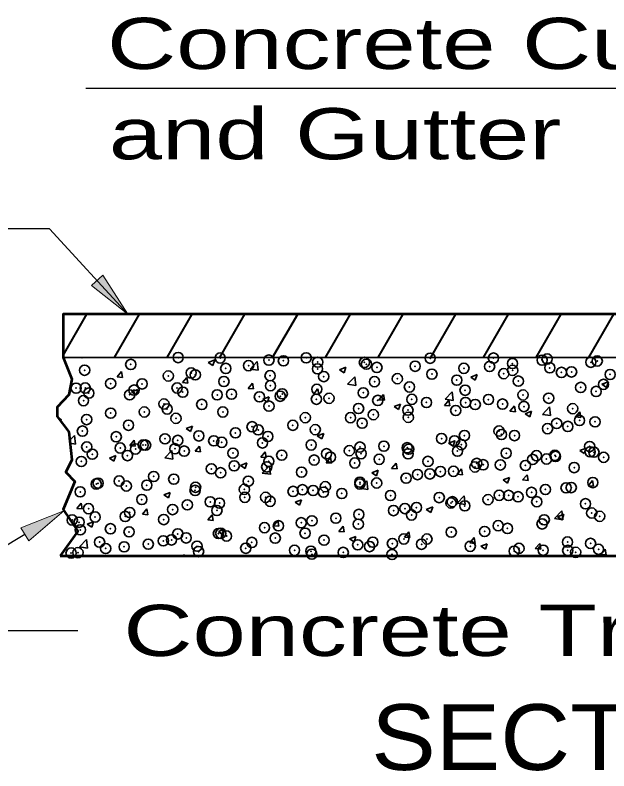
# Model space of a CAD drawing. Extents: x 14 to 49.3, y 28 to 50.
# Drawn here: x 25.937 to 27.563, y 46.498 to 48.567 of the extents above; entities that cross this region are included whole.
import ezdxf

# ---------------------------------------------------------------- set-up
doc = ezdxf.new("R2010")
doc.units = 0
doc.header["$LTSCALE"] = 0.056
doc.header["$PDMODE"] = 32
doc.header["$PDSIZE"] = 0.028
doc.layers.add('1', color=7, linetype='Continuous', lineweight=35)
doc.layers.add('3', color=7, linetype='Continuous', lineweight=13)

msp = doc.modelspace()

# ---------------------------------------------------------------- hatches: boundary and pattern name
at = {"layer": '3'}
for points in [[(26.17692, 47.85458), (26.14625, 47.8265), (26.246, 47.74833), (26.246, 47.74833)], [(25.95292, 47.16325), (25.97433, 47.1275), (26.07075, 47.20975), (26.07075, 47.20975)]]:
    msp.add_hatch(color=256, dxfattribs=at).paths.add_polyline_path(points)

# ---------------------------------------------------------------- linework, layer by layer
at = {"layer": '1', "lineweight": 40}
for p, q in [((26.06825, 47.63525), (26.1335, 47.74833)), ((26.20925, 47.62942), (26.27783, 47.74833)), ((26.35358, 47.62942), (26.42217, 47.74833)), ((26.49792, 47.62942), (26.5665, 47.74833)), ((26.64225, 47.62942), (26.71083, 47.74833)), ((26.78658, 47.62942), (26.85517, 47.74833)), ((26.93092, 47.62942), (26.9995, 47.74833)), ((27.07525, 47.62942), (27.14383, 47.74833)), ((27.21958, 47.62942), (27.28817, 47.74833)), ((27.36392, 47.62942), (27.4325, 47.74833)), ((27.50825, 47.62942), (27.57683, 47.74833))]:
    msp.add_line(p, q, dxfattribs=at)
at = {"layer": '1'}
for p, q in [((28.99683, 47.62942), (26.06825, 47.62942)), ((26.11692, 47.62942), (26.11925, 47.62783)), ((26.11925, 47.62783), (26.11975, 47.62942)), ((26.46608, 47.61625), (26.48358, 47.623)), ((26.46608, 47.61625), (26.4785, 47.60783)), ((26.4785, 47.60783), (26.48358, 47.62292)), ((26.58058, 47.59808), (26.60008, 47.61833)), ((26.60283, 47.59458), (26.60008, 47.61833)), ((26.58058, 47.59808), (26.60283, 47.59458)), ((26.82533, 47.59625), (26.84283, 47.60292)), ((26.82533, 47.59625), (26.83783, 47.58783)), ((26.83783, 47.58783), (26.84292, 47.60292)), ((26.21617, 47.57658), (26.22825, 47.59092)), ((26.21617, 47.57658), (26.23108, 47.57525)), ((26.23108, 47.57525), (26.22825, 47.59092)), ((26.3955, 47.56083), (26.4075, 47.57525)), ((26.41042, 47.55958), (26.40758, 47.57525)), ((26.84742, 47.55667), (26.86692, 47.577)), ((26.86967, 47.55325), (26.86692, 47.577)), ((27.18467, 47.57617), (27.20217, 47.58292)), ((27.18467, 47.57617), (27.19708, 47.56783)), ((27.19708, 47.56783), (27.20217, 47.58292)), ((26.3955, 47.56083), (26.41042, 47.55958)), ((26.57483, 47.54517), (26.58683, 47.55958)), ((26.58975, 47.54383), (26.58683, 47.5595)), ((26.84742, 47.55667), (26.86967, 47.55325)), ((27.54392, 47.55617), (27.56142, 47.56292)), ((27.54392, 47.55617), (27.55633, 47.54775)), ((27.55642, 47.54775), (27.56142, 47.56292)), ((26.256, 47.53558), (26.2735, 47.54233)), ((26.256, 47.53558), (26.2685, 47.52725)), ((26.2685, 47.52725), (26.27358, 47.54233)), ((26.57483, 47.54517), (26.58975, 47.54392)), ((26.75408, 47.5295), (26.76617, 47.54383)), ((26.76908, 47.52817), (26.76617, 47.54383)), ((27.11425, 47.51533), (27.13367, 47.53558)), ((27.1365, 47.51183), (27.13367, 47.53558)), ((26.61533, 47.51558), (26.63283, 47.52233)), ((26.61533, 47.51558), (26.62775, 47.50717)), ((26.62775, 47.50717), (26.63283, 47.52233)), ((26.75408, 47.5295), (26.76908, 47.52817)), ((26.93342, 47.51383), (26.9455, 47.52817)), ((26.93342, 47.51383), (26.94833, 47.5125)), ((26.94842, 47.5125), (26.9455, 47.52817)), ((27.11275, 47.49808), (27.12483, 47.5125)), ((27.11425, 47.51533), (27.13642, 47.51183)), ((27.12767, 47.49683), (27.12483, 47.5125)), ((26.97458, 47.49558), (26.99208, 47.50225)), ((26.97458, 47.49558), (26.987, 47.48717)), ((26.98708, 47.48717), (26.99208, 47.50225)), ((27.11275, 47.49808), (27.12767, 47.49683)), ((27.29208, 47.48242), (27.30408, 47.49683)), ((27.307, 47.48108), (27.30408, 47.49675)), ((27.381, 47.47392), (27.4005, 47.49425)), ((27.40325, 47.4705), (27.4005, 47.49425)), ((27.29208, 47.48242), (27.307, 47.48108)), ((27.33392, 47.4755), (27.35142, 47.48225)), ((27.33392, 47.4755), (27.34633, 47.46717)), ((27.34633, 47.46717), (27.35142, 47.48225)), ((27.381, 47.47392), (27.40325, 47.4705)), ((27.47133, 47.46675), (27.48342, 47.48108)), ((27.48633, 47.46542), (27.48342, 47.48108)), ((26.05842, 47.45975), (26.0635, 47.46167)), ((26.0615, 47.45575), (26.0635, 47.46167)), ((27.47133, 47.46675), (27.48633, 47.46542)), ((26.40525, 47.43492), (26.42275, 47.44167)), ((26.40525, 47.43492), (26.41767, 47.42658)), ((26.41767, 47.42658), (26.42275, 47.44167)), ((26.08683, 47.40292), (26.09958, 47.41625)), ((26.10233, 47.3925), (26.09958, 47.41617)), ((26.7645, 47.41492), (26.78208, 47.42167)), ((26.7645, 47.41492), (26.777, 47.40658)), ((26.777, 47.4065), (26.78208, 47.42167)), ((26.08767, 47.39475), (26.10233, 47.3925)), ((26.25083, 47.3885), (26.26292, 47.40283)), ((26.25083, 47.3885), (26.26583, 47.38717)), ((26.26583, 47.38717), (26.26292, 47.40283)), ((26.43017, 47.37283), (26.44225, 47.38717)), ((26.44517, 47.3715), (26.44225, 47.38717)), ((27.12383, 47.39492), (27.14133, 47.40167)), ((27.12383, 47.39492), (27.13625, 47.3865)), ((27.13625, 47.3865), (27.14133, 47.40158)), ((26.34692, 47.3545), (26.36642, 47.37483)), ((26.34692, 47.3545), (26.36642, 47.37483)), ((26.36917, 47.35108), (26.36642, 47.37483)), ((26.43017, 47.37283), (26.44508, 47.3715)), ((26.6095, 47.35717), (26.6215, 47.3715)), ((26.62442, 47.35583), (26.62158, 47.3715)), ((27.48308, 47.37492), (27.50058, 47.38158)), ((27.48308, 47.37492), (27.4955, 47.3665)), ((27.49558, 47.3665), (27.50058, 47.38158)), ((26.19517, 47.35433), (26.21267, 47.361)), ((26.19517, 47.35433), (26.20767, 47.34592)), ((26.20767, 47.34592), (26.21275, 47.361)), ((26.34692, 47.3545), (26.36917, 47.35108)), ((26.6095, 47.35717), (26.62442, 47.35583)), ((26.78883, 47.34142), (26.80083, 47.35583)), ((26.80375, 47.34017), (26.80083, 47.35583)), ((26.5545, 47.33433), (26.572, 47.341)), ((26.5545, 47.33433), (26.56692, 47.32592)), ((26.56692, 47.32592), (26.572, 47.341)), ((26.61375, 47.31317), (26.63325, 47.33342)), ((26.636, 47.30967), (26.63325, 47.33342)), ((26.78883, 47.34142), (26.80375, 47.34017)), ((26.96808, 47.32575), (26.98017, 47.34008)), ((26.96808, 47.32575), (26.98308, 47.32442)), ((26.98308, 47.32442), (26.98017, 47.34008)), ((27.14742, 47.31008), (27.1595, 47.32442)), ((27.16242, 47.30875), (27.1595, 47.32442)), ((26.61375, 47.31317), (26.636, 47.30975)), ((26.91375, 47.31425), (26.93125, 47.321)), ((26.91375, 47.31425), (26.92617, 47.30592)), ((26.92625, 47.30592), (26.93125, 47.321)), ((27.14742, 47.31008), (27.16233, 47.30875)), ((27.32675, 47.29442), (27.33883, 47.30875)), ((27.34167, 47.29308), (27.33883, 47.30875)), ((26.88058, 47.27175), (26.9, 47.29208)), ((26.90283, 47.26833), (26.9, 47.29208)), ((27.27308, 47.29425), (27.29058, 47.301)), ((27.27308, 47.29425), (27.2855, 47.28583)), ((27.2855, 47.28583), (27.29058, 47.301)), ((27.32675, 47.29442), (27.34167, 47.29308)), ((27.50608, 47.27867), (27.51808, 47.29308)), ((27.521, 47.27742), (27.51817, 47.29308)), ((26.88058, 47.27175), (26.90275, 47.26833)), ((27.50608, 47.27867), (27.521, 47.27742)), ((26.34442, 47.25367), (26.36192, 47.26042)), ((26.34442, 47.25367), (26.35683, 47.24525)), ((26.35692, 47.24525), (26.36192, 47.26042)), ((27.14733, 47.23042), (27.16683, 47.25067)), ((27.16958, 47.22692), (27.16683, 47.25067)), ((26.10625, 47.21617), (26.11825, 47.2305)), ((26.12117, 47.21483), (26.11833, 47.2305)), ((26.70367, 47.23367), (26.72125, 47.24033)), ((26.70367, 47.23367), (26.71617, 47.22525)), ((26.71617, 47.22525), (26.72125, 47.24033)), ((27.14733, 47.23042), (27.16958, 47.22692)), ((26.10625, 47.21617), (26.12117, 47.21483)), ((26.2855, 47.2005), (26.29758, 47.21483)), ((26.2855, 47.2005), (26.3005, 47.19917)), ((26.3005, 47.19917), (26.29758, 47.21483)), ((27.063, 47.21358), (27.0805, 47.22033)), ((27.063, 47.21358), (27.07542, 47.20525)), ((27.07542, 47.20525), (27.0805, 47.22033)), ((27.41417, 47.189), (27.43367, 47.20933)), ((27.42225, 47.19358), (27.43975, 47.20033)), ((27.43642, 47.18558), (27.43367, 47.20933)), ((27.43475, 47.18517), (27.43983, 47.20033)), ((26.13433, 47.173), (26.15183, 47.17975)), ((26.14683, 47.16467), (26.15192, 47.17975)), ((26.46483, 47.18475), (26.47692, 47.19917)), ((26.46483, 47.18475), (26.47983, 47.1835)), ((26.47983, 47.18342), (26.47692, 47.19917)), ((26.64417, 47.16908), (26.65625, 47.18342)), ((26.65917, 47.16775), (26.65625, 47.18342)), ((27.41417, 47.189), (27.43642, 47.18558)), ((27.42225, 47.19358), (27.43467, 47.18525)), ((26.13433, 47.173), (26.14683, 47.16467)), ((26.49367, 47.153), (26.51117, 47.15975)), ((26.50608, 47.14458), (26.51117, 47.15975)), ((26.64417, 47.16908), (26.65908, 47.16775)), ((26.8235, 47.15342), (26.8355, 47.16775)), ((26.83842, 47.15208), (26.83558, 47.16775)), ((26.49367, 47.153), (26.50608, 47.14458)), ((26.8235, 47.15342), (26.83842, 47.15208)), ((26.85292, 47.133), (26.87042, 47.13967)), ((26.86542, 47.12458), (26.87042, 47.13967)), ((27.00283, 47.13775), (27.01483, 47.15208)), ((27.00283, 47.13775), (27.01775, 47.13642)), ((27.01775, 47.13642), (27.01483, 47.15208)), ((26.11325, 47.111), (26.13275, 47.13133)), ((26.1355, 47.10758), (26.13275, 47.13133)), ((26.85292, 47.133), (26.86533, 47.12458)), ((27.18208, 47.122), (27.19417, 47.13642)), ((27.18208, 47.122), (27.19708, 47.12075)), ((27.19708, 47.12067), (27.19417, 47.13642)), ((27.21225, 47.113), (27.22975, 47.11967)), ((27.22467, 47.10458), (27.22975, 47.11967)), ((27.36142, 47.10633), (27.3735, 47.12067)), ((27.37642, 47.105), (27.3735, 47.12067)), ((26.11325, 47.111), (26.1355, 47.10758)), ((27.21225, 47.113), (27.22467, 47.10458)), ((27.36142, 47.10633), (27.37642, 47.105)), ((27.54075, 47.09067), (27.55283, 47.105)), ((27.55567, 47.08933), (27.55283, 47.105)), ((26.39592, 47.08617), (26.39958, 47.08992)), ((26.4, 47.08617), (26.39958, 47.08992)), ((27.54075, 47.09067), (27.55567, 47.08933))]:
    msp.add_line(p, q, dxfattribs=at)
at = {"layer": '1', "lineweight": 53}
for points in [[(26.06008, 47.08617), (29.45792, 47.08617), (29.45792, 47.9605), (29.44175, 48.03692), (29.40133, 48.07933), (29.17475, 48.07933), (29.11008, 48.05392), (29.08583, 47.9945), (28.99683, 47.62942)], [(29.02583, 47.74833), (26.06825, 47.74833), (26.06825, 47.62942)], [(26.06825, 47.62942), (26.0925, 47.57), (26.08442, 47.52758), (26.052, 47.49367), (26.052, 47.46817), (26.08442, 47.42575), (26.0925, 47.34933), (26.07633, 47.31533), (26.10058, 47.28992), (26.06825, 47.2135), (26.10867, 47.15408), (26.06008, 47.08617)]]:
    msp.add_lwpolyline(points, dxfattribs=at)
at = {"layer": '1'}
for p in [(26.38367, 47.62942), (26.49867, 47.62825), (26.63208, 47.62258), (26.67175, 47.6205), (26.73433, 47.62875), (27.07358, 47.6275), (27.24667, 47.628), (27.38008, 47.62233), (27.39358, 47.62558), (26.25375, 47.61067), (26.51392, 47.59967), (26.57633, 47.60725), (26.76558, 47.61692), (26.89342, 47.61608), (26.899, 47.61133), (26.92783, 47.60242), (27.03242, 47.60567), (27.16592, 47.6), (27.23633, 47.60483), (27.29892, 47.61308), (27.40117, 47.60125), (27.51358, 47.61667), (27.531, 47.62), (26.1275, 47.59467), (26.35658, 47.579), (26.41917, 47.58725), (26.4305, 47.58225), (26.63525, 47.57975), (26.76508, 47.5985), (27.07842, 47.58408), (27.27492, 47.58525), (27.29933, 47.59442), (27.43283, 47.58875), (27.46067, 47.59008), (27.56625, 47.58308), (26.50892, 47.56375), (26.782, 47.57742), (26.92117, 47.56333), (26.98375, 47.57158), (27.1465, 47.56767), (27.31492, 47.565), (26.10408, 47.54575), (26.12925, 47.546), (26.19875, 47.55817), (26.26275, 47.54033), (26.28475, 47.55725), (26.38058, 47.54617), (26.63625, 47.55242), (26.76325, 47.54258), (27.01667, 47.54892), (27.16908, 47.54), (27.48567, 47.54775), (27.54825, 47.556), (26.13892, 47.53225), (26.25075, 47.52742), (26.39617, 47.53475), (26.49042, 47.52733), (26.52967, 47.52908), (26.606, 47.52192), (26.66308, 47.52342), (26.66858, 47.53008), (26.79658, 47.51783), (26.89042, 47.53292), (27.32783, 47.527), (27.39808, 47.518), (27.528, 47.53675), (26.1245, 47.51142), (26.34467, 47.50233), (26.44808, 47.50108), (26.63217, 47.49658), (26.762, 47.51525), (26.93, 47.51217), (27.02333, 47.515), (27.0635, 47.5065), (27.17058, 47.50625), (27.19692, 47.50092), (27.23317, 47.5145), (27.27183, 47.502), (26.19883, 47.47733), (26.29083, 47.48042), (26.35342, 47.48858), (26.50592, 47.4805), (26.8775, 47.48992), (27.01267, 47.4855), (27.1435, 47.48442), (27.33033, 47.49525), (27.46383, 47.48958), (26.133, 47.45958), (26.37758, 47.46292), (26.73167, 47.46492), (26.85542, 47.46475), (26.918, 47.473), (27.01367, 47.46567), (27.4825, 47.45742), (26.24767, 47.44417), (26.58592, 47.43992), (26.6975, 47.444), (26.88733, 47.44967), (27.39508, 47.43483), (27.41992, 47.44917), (27.45033, 47.44092), (27.52492, 47.45358), (26.12142, 47.42817), (26.44008, 47.41483), (26.54025, 47.42325), (26.60283, 47.4315), (26.759, 47.43208), (27.16733, 47.41592), (27.26208, 47.42833), (27.26883, 47.41883), (27.30458, 47.41583), (26.21408, 47.41258), (26.3475, 47.407), (26.38233, 47.4025), (26.48092, 47.40133), (26.50283, 47.39733), (26.61442, 47.39567), (26.62917, 47.41333), (27.10475, 47.40767), (27.14042, 47.40117), (26.13333, 47.38467), (26.22508, 47.38175), (26.26675, 47.379), (26.28767, 47.39), (26.29433, 47.38983), (26.3745, 47.37975), (26.40025, 47.37342), (26.74783, 47.39008), (26.85225, 47.37442), (26.88133, 47.38442), (26.94692, 47.38683), (27.01058, 47.38242), (27.01475, 47.37875), (27.14825, 47.37317), (27.15875, 47.39083), (27.51025, 47.386), (26.1485, 47.36483), (26.24467, 47.361), (26.53367, 47.36775), (26.66708, 47.36208), (26.78967, 47.36617), (26.80058, 47.3565), (26.88433, 47.36642), (27.013, 47.36583), (27.28167, 47.3675), (27.3645, 47.36092), (27.392, 47.35158), (27.41517, 47.36183), (27.41675, 47.35875), (27.51142, 47.37125), (27.52192, 47.37033), (27.54858, 47.35625), (26.11842, 47.345), (26.53708, 47.33292), (26.63175, 47.34533), (26.75592, 47.34883), (26.86717, 47.34075), (26.934, 47.35083), (27.0675, 47.34517), (27.20092, 47.33958), (27.21867, 47.33592), (27.26575, 47.33558), (27.33442, 47.33392), (27.35417, 47.3505), (26.4745, 47.32467), (26.49983, 47.31408), (26.62608, 47.33008), (26.72142, 47.31575), (27.07292, 47.31092), (27.10158, 47.31725), (27.13742, 47.318), (27.19625, 47.32975), (27.46783, 47.32825), (26.22192, 47.29142), (26.31658, 47.30392), (26.3715, 47.2965), (26.57558, 47.29075), (27.00758, 47.29925), (27.039, 47.30908), (26.15933, 47.28317), (26.16433, 47.2855), (26.24167, 47.27775), (26.29775, 47.27992), (26.43125, 47.27425), (26.56467, 47.26858), (26.78642, 47.27583), (26.88117, 47.28825), (26.88125, 47.28325), (26.92708, 47.28592), (27.44567, 47.27267), (27.45992, 47.2735), (27.51883, 47.28708), (26.11533, 47.26175), (26.42983, 47.26567), (26.69817, 47.263), (26.72383, 47.26758), (26.75292, 47.26558), (26.78125, 47.26083), (26.83158, 47.25733), (26.965, 47.25167), (27.26275, 47.25233), (27.28842, 47.25192), (27.31417, 47.24842), (27.351, 47.26017), (27.389, 47.26833), (26.284, 47.24067), (26.47125, 47.23433), (26.49683, 47.23083), (26.566, 47.24675), (26.62308, 47.24683), (26.6355, 47.23583), (27.0985, 47.24608), (27.1305, 47.23117), (27.13433, 47.23475), (27.23192, 47.24042), (27.36542, 47.23475), (27.49883, 47.22917), (26.13817, 47.21567), (26.36842, 47.21325), (26.40867, 47.22608), (26.48967, 47.21083), (26.97325, 47.21042), (27.0045, 47.216), (27.03583, 47.21867), (27.16833, 47.22342), (26.15617, 47.19283), (26.23858, 47.1945), (26.25083, 47.20525), (26.81533, 47.18967), (26.87825, 47.2), (27.02258, 47.19842), (27.51583, 47.20383), (27.53775, 47.19483), (26.09358, 47.18458), (26.11233, 47.1785), (26.34392, 47.18575), (26.65808, 47.16892), (26.72067, 47.17717), (26.74992, 47.18242), (26.87675, 47.17333), (27.25967, 47.16908), (27.37992, 47.174), (27.38592, 47.18517), (26.11558, 47.15775), (26.19808, 47.16075), (26.24908, 47.15217), (26.3825, 47.1465), (26.49375, 47.14767), (26.50017, 47.14817), (26.62, 47.16367), (26.731, 47.14833), (27.13133, 47.1515), (27.22267, 47.15333), (27.28525, 47.16158), (26.16833, 47.12417), (26.34292, 47.1275), (26.36542, 47.13008), (26.4055, 47.13567), (26.516, 47.14083), (26.64942, 47.13525), (26.78292, 47.12958), (26.91633, 47.12392), (27.0015, 47.13275), (27.06475, 47.13258), (27.44967, 47.12433), (26.18508, 47.10667), (26.23558, 47.11133), (26.30175, 47.11858), (26.43525, 47.11292), (26.56867, 47.10725), (26.58517, 47.12333), (26.87517, 47.11675), (26.9075, 47.11183), (26.97008, 47.12008), (27.04983, 47.11833), (27.18325, 47.11267), (27.31675, 47.107), (27.51275, 47.12067), (27.53458, 47.1045), (26.09033, 47.09425), (26.10925, 47.09533), (26.43942, 47.09825), (26.70217, 47.10167), (26.74683, 47.09917), (26.74958, 47.09108), (26.83558, 47.096), (26.96908, 47.09033), (27.30383, 47.09925), (27.38292, 47.10192), (27.45017, 47.10142), (27.472, 47.09625)]:
    msp.add_point(p, dxfattribs=at)
at = {"layer": '3', "lineweight": 25}
for points in [[(28.64, 47.4555), (28.08833, 48.36625), (26.13083, 48.36625)], [(26.246, 47.74833), (26.03083, 47.98208), (24.39125, 47.98208)], [(25.96367, 47.14533), (25.52617, 46.88242), (26.10867, 46.88242)]]:
    msp.add_lwpolyline(points, dxfattribs=at)
at = {"layer": '3'}
for points in [[(26.17692, 47.85458), (26.14625, 47.8265), (26.246, 47.74833), (26.246, 47.74833)], [(25.95292, 47.16325), (25.97433, 47.1275), (26.07075, 47.20975), (26.07075, 47.20975)]]:
    msp.add_lwpolyline(points, close=True, dxfattribs=at)

# ---------------------------------------------------------------- texts
for s, height, width, p in [('Concrete Curb', 0.14, 1.4, (26.18892, 48.41958)), ('and Gutter', 0.14, 1.4, (26.19383, 48.17233)), ('Concrete Transition Pavement', 0.14, 1.4, (26.23367, 46.81242)), ('SECTION D-D', 0.18, 1.1, (26.91225, 46.50033))]:
    msp.add_text(s, height=height, dxfattribs=dict(at, width=width)).set_placement(p)

doc.saveas('drawing.dxf')
